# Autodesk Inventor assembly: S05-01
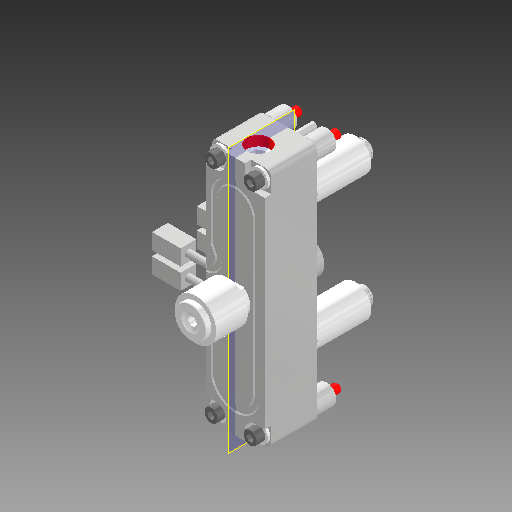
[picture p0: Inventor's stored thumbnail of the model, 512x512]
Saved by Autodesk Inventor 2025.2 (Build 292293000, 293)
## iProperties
Created: 2025-04
Part Number: S05-01
Document SubType Name: Assembly
Designer: Patrik
Description: Systém horkého vtoku
Stock Number: EH 6000
Author: Patrik
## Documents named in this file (28)
- C:\Users\Patrik\Documents\Skola\Bakalarska prace\Prakticka cast\Meusburger - sestava - horky vtok\Temperacni system.iam
- C:\Users\Patrik\Documents\Skola\Bakalarska prace\Prakticka cast\Meusburger - sestava - horky vtok\E 2071_9_47.ipt
- C:\Users\Patrik\Documents\Skola\Bakalarska prace\Prakticka cast\Meusburger - sestava - horky vtok\E 2071_9_48.ipt
- C:\Users\Patrik\Documents\Skola\Bakalarska prace\Prakticka cast\Meusburger - sestava - horky vtok\E 2071_9_49.ipt
- C:\Users\Patrik\Documents\Skola\Bakalarska prace\Prakticka cast\Meusburger - sestava - horky vtok\E 2071_9_50.ipt
- C:\Users\Patrik\Documents\Skola\Bakalarska prace\Prakticka cast\Meusburger - sestava - horky vtok\E 2071_9_51.ipt
- C:\Users\Patrik\Documents\Skola\Bakalarska prace\Prakticka cast\Meusburger - sestava - horky vtok\E 2071_9_52.ipt
- C:\Users\Patrik\Documents\Skola\Bakalarska prace\Prakticka cast\Meusburger - sestava - horky vtok\E 2071_9_53.ipt
- C:\Users\Patrik\Documents\Skola\Bakalarska prace\Prakticka cast\Meusburger - sestava - horky vtok\E 2071_9_54.ipt
- C:\Users\Patrik\Documents\Skola\Bakalarska prace\Prakticka cast\Meusburger - sestava - horky vtok\E 2071_9_55.ipt
- C:\Users\Patrik\Documents\Skola\Bakalarska prace\Prakticka cast\Meusburger - sestava - horky vtok\E 2071_9_56.ipt
- C:\Users\Patrik\Documents\Skola\Bakalarska prace\Prakticka cast\Meusburger - sestava - horky vtok\E 2071_9_57.ipt
- C:\Users\Patrik\Documents\Skola\Bakalarska prace\Prakticka cast\Meusburger - sestava - horky vtok\E 2071_9_58.ipt
- C:\Users\Patrik\Documents\Skola\Bakalarska prace\Prakticka cast\Meusburger - sestava - horky vtok\E 2071_9_59.ipt
- C:\Users\Patrik\Documents\Skola\Bakalarska prace\Prakticka cast\Meusburger - sestava - horky vtok\E 2071_9_60.ipt
- C:\Users\Patrik\Documents\Skola\Bakalarska prace\Prakticka cast\Meusburger - sestava - horky vtok\E 2071_9_61.ipt
- C:\Users\Patrik\Documents\Skola\Bakalarska prace\Prakticka cast\Meusburger - sestava - horky vtok\E 2071_9_62.ipt
- C:\Users\Patrik\Documents\Skola\Bakalarska prace\Prakticka cast\Meusburger - sestava - horky vtok\E 2071_9_63.ipt
- C:\Users\Patrik\Documents\Skola\Bakalarska prace\Prakticka cast\Meusburger - sestava - horky vtok\E 2071_9_64.ipt
- C:\Users\Patrik\Documents\Skola\Bakalarska prace\Prakticka cast\Meusburger - sestava - horky vtok\E 2071_9_65.ipt
- C:\Users\Patrik\Documents\Skola\Bakalarska prace\Prakticka cast\Meusburger - sestava - horky vtok\E 2071_9_66.ipt
- C:\Users\Patrik\Documents\Skola\Bakalarska prace\Prakticka cast\Meusburger - sestava - horky vtok\E 2071_9_67.ipt
- C:\Users\Patrik\Documents\Skola\Bakalarska prace\Prakticka cast\Meusburger - sestava - horky vtok\E 2071_9_68.ipt
- C:\Users\Patrik\Documents\Skola\Bakalarska prace\Prakticka cast\Meusburger - sestava - horky vtok\E 2071_9_69.ipt
- C:\Users\Patrik\Documents\Skola\Bakalarska prace\Prakticka cast\Meusburger - sestava - horky vtok\E 2071_9_70.ipt
- C:\Users\Patrik\Documents\Skola\Bakalarska prace\Prakticka cast\Meusburger - sestava - horky vtok\E 2071_9_71.ipt
- C:\Users\Patrik\Documents\Skola\Bakalarska prace\Prakticka cast\Meusburger - sestava - horky vtok\E 2071_9_72.ipt
- C:\Users\Patrik\Documents\Skola\Bakalarska prace\Prakticka cast\Meusburger - sestava - horky vtok\E 2071_9_73.ipt
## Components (27 placed, 27 different names)
1. E 2071_9_53:1
2. E 2071_9_63:1
3. E 2071_9_68:1
4. E 2071_9_67:1
5. E 2071_9_56:1
6. E 2071_9_55:1
7. E 2071_9_48:1
8. E 2071_9_49:1
9. E 2071_9_50:1
10. E 2071_9_51:1
11. E 2071_9_52:1
12. E 2071_9_54:1
13. E 2071_9_57:1
14. E 2071_9_58:1
15. E 2071_9_59:1
16. E 2071_9_60:1
17. E 2071_9_61:1
18. E 2071_9_62:1
19. E 2071_9_64:1
20. E 2071_9_65:1
21. E 2071_9_66:1
22. E 2071_9_69:1 — Vložit:26
23. E 2071_9_70:1
24. E 2071_9_71:1
25. E 2071_9_72:1
26. E 2071_9_73:1
27. E 2071_9_74:1
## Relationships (1: Insert 1)
- Vložit:26 [Insert]: E 2071_9_69:1
